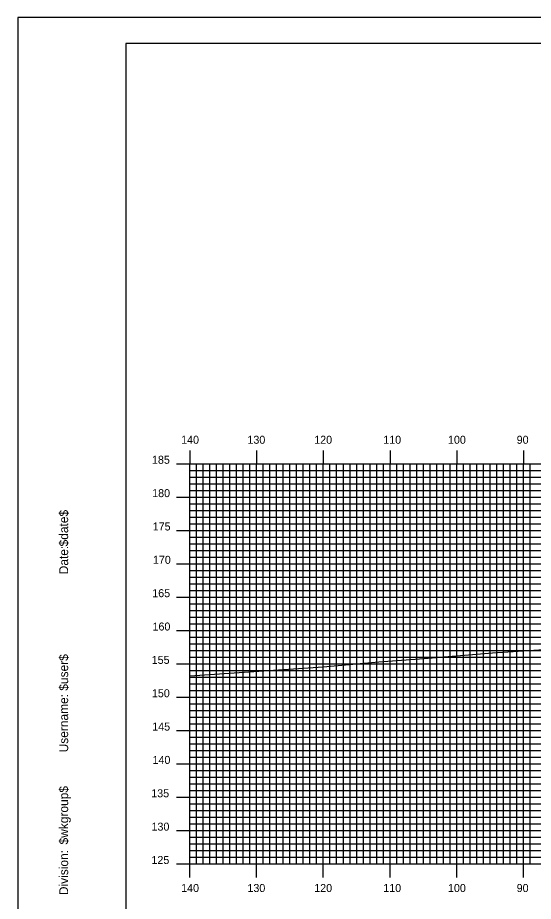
# Model space of a CAD drawing. Extents: x 1783828 to 1784171, y 442591 to 442811.
# Drawn here: x 1783827.7 to 1783905, y 442678.1 to 442810.5 of the extents above; entities that cross this region are included whole.
import ezdxf

# ---------------------------------------------------------------- set-up
doc = ezdxf.new("R2010")
doc.units = 0
for name, color, linetype in [('BORDER', 7, 'Continuous'), ('H_V ANNOTATION', 7, 'Continuous'), ('MAJOR', 7, 'Continuous'), ('MINOR', 7, 'Continuous'), ('PLOT BOUNDARY', 7, 'Continuous'), ('S_Roadway_Centerline', 7, 'Continuous')]:
    doc.layers.add(name, color=color, linetype=linetype)

msp = doc.modelspace()

# ---------------------------------------------------------------- linework, layer by layer
at = {"layer": 'BORDER'}
msp.add_lwpolyline([(1783843.89, 442596.67), (1784163.89, 442596.67), (1784163.89, 442806.67), (1783843.89, 442806.67)], close=True, dxfattribs=at)
at = {"layer": 'MAJOR'}
for p, q in [((1783853.49, 442745.67), (1783853.49, 442743.67)), ((1783863.49, 442745.67), (1783863.49, 442743.67)), ((1783873.49, 442745.67), (1783873.49, 442743.67)), ((1783883.49, 442745.67), (1783883.49, 442743.67)), ((1783893.49, 442745.67), (1783893.49, 442743.67)), ((1783903.49, 442745.67), (1783903.49, 442743.67)), ((1783851.48, 442743.67), (1783853.49, 442743.67)), ((1783853.49, 442743.67), (1784133.49, 442743.67)), ((1783853.49, 442683.67), (1783853.49, 442743.67)), ((1783853.49, 442683.67), (1783853.49, 442743.67)), ((1783853.49, 442743.67), (1784133.49, 442743.67)), ((1783863.49, 442683.67), (1783863.49, 442743.67)), ((1783873.49, 442683.67), (1783873.49, 442743.67)), ((1783883.49, 442683.67), (1783883.49, 442743.67)), ((1783893.49, 442683.67), (1783893.49, 442743.67)), ((1783903.49, 442683.67), (1783903.49, 442743.67)), ((1783851.48, 442738.67), (1783853.49, 442738.67)), ((1783853.49, 442738.67), (1784133.49, 442738.67)), ((1783851.48, 442733.67), (1783853.49, 442733.67)), ((1783853.49, 442733.67), (1784133.49, 442733.67)), ((1783851.48, 442728.67), (1783853.49, 442728.67)), ((1783853.49, 442728.67), (1784133.49, 442728.67)), ((1783851.48, 442723.67), (1783853.49, 442723.67)), ((1783853.49, 442723.67), (1784133.49, 442723.67)), ((1783851.48, 442718.67), (1783853.49, 442718.67)), ((1783853.49, 442718.67), (1784133.49, 442718.67)), ((1783851.48, 442713.67), (1783853.49, 442713.67)), ((1783853.49, 442713.67), (1784133.49, 442713.67)), ((1783851.48, 442708.67), (1783853.49, 442708.67)), ((1783853.49, 442708.67), (1784133.49, 442708.67)), ((1783851.48, 442703.67), (1783853.49, 442703.67)), ((1783853.49, 442703.67), (1784133.49, 442703.67)), ((1783851.48, 442698.67), (1783853.49, 442698.67)), ((1783853.49, 442698.67), (1784133.49, 442698.67)), ((1783851.48, 442693.67), (1783853.49, 442693.67)), ((1783853.49, 442693.67), (1784133.49, 442693.67)), ((1783851.48, 442688.67), (1783853.49, 442688.67)), ((1783853.49, 442688.67), (1784133.49, 442688.67)), ((1783851.48, 442683.67), (1783853.49, 442683.67)), ((1783853.49, 442683.67), (1784133.49, 442683.67)), ((1783853.49, 442683.67), (1784133.49, 442683.67)), ((1783853.49, 442681.66), (1783853.49, 442683.67)), ((1783863.49, 442681.66), (1783863.49, 442683.67)), ((1783873.49, 442681.66), (1783873.49, 442683.67)), ((1783883.49, 442681.66), (1783883.49, 442683.67)), ((1783893.49, 442681.66), (1783893.49, 442683.67)), ((1783903.49, 442681.66), (1783903.49, 442683.67))]:
    msp.add_line(p, q, dxfattribs=at)
at = {"layer": 'MINOR'}
for p, q in [((1783854.49, 442683.67), (1783854.49, 442743.67)), ((1783855.49, 442683.67), (1783855.49, 442743.67)), ((1783856.49, 442683.67), (1783856.49, 442743.67)), ((1783857.49, 442683.67), (1783857.49, 442743.67)), ((1783858.49, 442683.67), (1783858.49, 442743.67)), ((1783859.49, 442683.67), (1783859.49, 442743.67)), ((1783860.49, 442683.67), (1783860.49, 442743.67)), ((1783861.49, 442683.67), (1783861.49, 442743.67)), ((1783862.49, 442683.67), (1783862.49, 442743.67)), ((1783864.49, 442683.67), (1783864.49, 442743.67)), ((1783865.49, 442683.67), (1783865.49, 442743.67)), ((1783866.49, 442683.67), (1783866.49, 442743.67)), ((1783867.49, 442683.67), (1783867.49, 442743.67)), ((1783868.49, 442683.67), (1783868.49, 442743.67)), ((1783869.49, 442683.67), (1783869.49, 442743.67)), ((1783870.49, 442683.67), (1783870.49, 442743.67)), ((1783871.49, 442683.67), (1783871.49, 442743.67)), ((1783872.49, 442683.67), (1783872.49, 442743.67)), ((1783874.49, 442683.67), (1783874.49, 442743.67)), ((1783875.49, 442683.67), (1783875.49, 442743.67)), ((1783876.49, 442683.67), (1783876.49, 442743.67)), ((1783877.49, 442683.67), (1783877.49, 442743.67)), ((1783878.49, 442683.67), (1783878.49, 442743.67)), ((1783879.49, 442683.67), (1783879.49, 442743.67)), ((1783880.49, 442683.67), (1783880.49, 442743.67)), ((1783881.49, 442683.67), (1783881.49, 442743.67)), ((1783882.49, 442683.67), (1783882.49, 442743.67)), ((1783884.49, 442683.67), (1783884.49, 442743.67)), ((1783885.49, 442683.67), (1783885.49, 442743.67)), ((1783886.49, 442683.67), (1783886.49, 442743.67)), ((1783887.49, 442683.67), (1783887.49, 442743.67)), ((1783888.49, 442683.67), (1783888.49, 442743.67)), ((1783889.49, 442683.67), (1783889.49, 442743.67)), ((1783890.49, 442683.67), (1783890.49, 442743.67)), ((1783891.49, 442683.67), (1783891.49, 442743.67)), ((1783892.49, 442683.67), (1783892.49, 442743.67)), ((1783894.49, 442683.67), (1783894.49, 442743.67)), ((1783895.49, 442683.67), (1783895.49, 442743.67)), ((1783896.49, 442683.67), (1783896.49, 442743.67)), ((1783897.49, 442683.67), (1783897.49, 442743.67)), ((1783898.49, 442683.67), (1783898.49, 442743.67)), ((1783899.49, 442683.67), (1783899.49, 442743.67)), ((1783900.49, 442683.67), (1783900.49, 442743.67)), ((1783901.49, 442683.67), (1783901.49, 442743.67)), ((1783902.49, 442683.67), (1783902.49, 442743.67)), ((1783904.49, 442683.67), (1783904.49, 442743.67)), ((1783853.49, 442742.67), (1784133.49, 442742.67)), ((1783853.49, 442742.67), (1783855.49, 442742.67)), ((1783853.49, 442741.67), (1784133.49, 442741.67)), ((1783853.49, 442741.67), (1783855.49, 442741.67)), ((1783853.49, 442740.67), (1784133.49, 442740.67)), ((1783853.49, 442740.67), (1783855.49, 442740.67)), ((1783853.49, 442739.67), (1784133.49, 442739.67)), ((1783853.49, 442739.67), (1783855.49, 442739.67)), ((1783853.49, 442737.67), (1784133.49, 442737.67)), ((1783853.49, 442737.67), (1783855.49, 442737.67)), ((1783853.49, 442736.67), (1784133.49, 442736.67)), ((1783853.49, 442736.67), (1783855.49, 442736.67)), ((1783853.49, 442735.67), (1784133.49, 442735.67)), ((1783853.49, 442735.67), (1783855.49, 442735.67)), ((1783853.49, 442734.67), (1784133.49, 442734.67)), ((1783853.49, 442734.67), (1783855.49, 442734.67)), ((1783853.49, 442732.67), (1784133.49, 442732.67)), ((1783853.49, 442732.67), (1783855.49, 442732.67)), ((1783853.49, 442731.67), (1784133.49, 442731.67)), ((1783853.49, 442731.67), (1783855.49, 442731.67)), ((1783853.49, 442730.67), (1784133.49, 442730.67)), ((1783853.49, 442730.67), (1783855.49, 442730.67)), ((1783853.49, 442729.67), (1784133.49, 442729.67)), ((1783853.49, 442729.67), (1783855.49, 442729.67)), ((1783853.49, 442727.67), (1784133.49, 442727.67)), ((1783853.49, 442727.67), (1783855.49, 442727.67)), ((1783853.49, 442726.67), (1784133.49, 442726.67)), ((1783853.49, 442726.67), (1783855.49, 442726.67)), ((1783853.49, 442725.67), (1784133.49, 442725.67)), ((1783853.49, 442725.67), (1783855.49, 442725.67)), ((1783853.49, 442724.67), (1784133.49, 442724.67)), ((1783853.49, 442724.67), (1783855.49, 442724.67)), ((1783853.49, 442722.67), (1784133.49, 442722.67)), ((1783853.49, 442722.67), (1783855.49, 442722.67)), ((1783853.49, 442721.67), (1784133.49, 442721.67)), ((1783853.49, 442721.67), (1783855.49, 442721.67)), ((1783853.49, 442720.67), (1784133.49, 442720.67)), ((1783853.49, 442720.67), (1783855.49, 442720.67)), ((1783853.49, 442719.67), (1784133.49, 442719.67)), ((1783853.49, 442719.67), (1783855.49, 442719.67)), ((1783853.49, 442717.67), (1784133.49, 442717.67)), ((1783853.49, 442717.67), (1783855.49, 442717.67)), ((1783853.49, 442716.67), (1784133.49, 442716.67)), ((1783853.49, 442716.67), (1783855.49, 442716.67)), ((1783853.49, 442715.67), (1784133.49, 442715.67)), ((1783853.49, 442715.67), (1783855.49, 442715.67)), ((1783853.49, 442714.67), (1784133.49, 442714.67)), ((1783853.49, 442714.67), (1783855.49, 442714.67)), ((1783853.49, 442712.67), (1784133.49, 442712.67)), ((1783853.49, 442712.67), (1783855.49, 442712.67)), ((1783853.49, 442711.67), (1784133.49, 442711.67)), ((1783853.49, 442711.67), (1783855.49, 442711.67)), ((1783853.49, 442710.67), (1784133.49, 442710.67)), ((1783853.49, 442710.67), (1783855.49, 442710.67)), ((1783853.49, 442709.67), (1784133.49, 442709.67)), ((1783853.49, 442709.67), (1783855.49, 442709.67)), ((1783853.49, 442707.67), (1784133.49, 442707.67)), ((1783853.49, 442707.67), (1783855.49, 442707.67)), ((1783853.49, 442706.67), (1784133.49, 442706.67)), ((1783853.49, 442706.67), (1783855.49, 442706.67)), ((1783853.49, 442705.67), (1784133.49, 442705.67)), ((1783853.49, 442705.67), (1783855.49, 442705.67)), ((1783853.49, 442704.67), (1784133.49, 442704.67)), ((1783853.49, 442704.67), (1783855.49, 442704.67)), ((1783853.49, 442702.67), (1784133.49, 442702.67)), ((1783853.49, 442702.67), (1783855.49, 442702.67)), ((1783853.49, 442701.67), (1784133.49, 442701.67)), ((1783853.49, 442701.67), (1783855.49, 442701.67)), ((1783853.49, 442700.67), (1784133.49, 442700.67)), ((1783853.49, 442700.67), (1783855.49, 442700.67)), ((1783853.49, 442699.67), (1784133.49, 442699.67)), ((1783853.49, 442699.67), (1783855.49, 442699.67)), ((1783853.49, 442697.67), (1784133.49, 442697.67)), ((1783853.49, 442697.67), (1783855.49, 442697.67)), ((1783853.49, 442696.67), (1784133.49, 442696.67)), ((1783853.49, 442696.67), (1783855.49, 442696.67)), ((1783853.49, 442695.67), (1784133.49, 442695.67)), ((1783853.49, 442695.67), (1783855.49, 442695.67)), ((1783853.49, 442694.67), (1784133.49, 442694.67)), ((1783853.49, 442694.67), (1783855.49, 442694.67)), ((1783853.49, 442692.67), (1784133.49, 442692.67)), ((1783853.49, 442692.67), (1783855.49, 442692.67)), ((1783853.49, 442691.67), (1784133.49, 442691.67)), ((1783853.49, 442691.67), (1783855.49, 442691.67)), ((1783853.49, 442690.67), (1784133.49, 442690.67)), ((1783853.49, 442690.67), (1783855.49, 442690.67)), ((1783853.49, 442689.67), (1784133.49, 442689.67)), ((1783853.49, 442689.67), (1783855.49, 442689.67)), ((1783853.49, 442687.67), (1784133.49, 442687.67)), ((1783853.49, 442687.67), (1783855.49, 442687.67)), ((1783853.49, 442686.67), (1784133.49, 442686.67)), ((1783853.49, 442686.67), (1783855.49, 442686.67)), ((1783853.49, 442685.67), (1784133.49, 442685.67)), ((1783853.49, 442685.67), (1783855.49, 442685.67)), ((1783853.49, 442684.67), (1784133.49, 442684.67)), ((1783853.49, 442684.67), (1783855.49, 442684.67))]:
    msp.add_line(p, q, dxfattribs=at)
at = {"layer": 'PLOT BOUNDARY'}
msp.add_lwpolyline([(1783827.7, 442590.55), (1784167.7, 442590.55), (1784167.7, 442810.55), (1783827.7, 442810.55)], close=True, dxfattribs=at)
at = {"layer": 'S_Roadway_Centerline'}
msp.add_lwpolyline([(1783853.49, 442711.87), (1783866.8, 442712.79), (1783873.47, 442713.23), (1783881.83, 442713.97), (1783888.58, 442714.48), (1783898.84, 442715.31), (1783911.18, 442716.14), (1783921.63, 442717.01), (1783927.95, 442717.72), (1783934.33, 442718.23), (1783951.44, 442719.75), (1783956.09, 442720.05), (1783969.81, 442721.39), (1783974.44, 442721.86), (1783978.27, 442722.15), (1783993.21, 442723.6), (1783997.05, 442724.08), (1784000.91, 442724.38), (1784017.73, 442725.69), (1784024.01, 442726.23), (1784032.25, 442727.12)], dxfattribs=at)

# ---------------------------------------------------------------- texts
at = {"layer": 'BORDER'}
for s, p in [('$date$', (1783835.26, 442731.28)), ('$date$', (1783835.26, 442731.28)), ('Date:', (1783835.26, 442727.1)), ('Date:', (1783835.26, 442727.1)), ('$user$', (1783835.26, 442709.65)), ('$user$', (1783835.26, 442709.65)), ('Username:', (1783835.26, 442700.4)), ('Username:', (1783835.26, 442700.4)), ('$wkgroup$', (1783835.26, 442686.6)), ('$wkgroup$', (1783835.26, 442686.6)), ('Division:', (1783835.26, 442679)), ('Division:', (1783835.26, 442679))]:
    msp.add_text(s, height=1.339, rotation=90, dxfattribs=at).set_placement(p)
at = {"layer": 'H_V ANNOTATION'}
for s, p in [('140', (1783852.19, 442746.67)), ('130', (1783862.12, 442746.67)), ('120', (1783872.13, 442746.67)), ('110', (1783882.47, 442746.67)), ('100', (1783892.17, 442746.67)), ('90', (1783902.46, 442746.67)), ('185', (1783847.82, 442743.67)), ('180', (1783847.85, 442738.67)), ('175', (1783847.93, 442733.67)), ('170', (1783847.96, 442728.67)), ('165', (1783847.86, 442723.67)), ('160', (1783847.9, 442718.67)), ('155', (1783847.78, 442713.67)), ('150', (1783847.81, 442708.67)), ('145', (1783847.86, 442703.67)), ('140', (1783847.9, 442698.67)), ('135', (1783847.71, 442693.67)), ('130', (1783847.75, 442688.67)), ('125', (1783847.74, 442683.67)), ('140', (1783852.19, 442679.47)), ('130', (1783862.12, 442679.47)), ('120', (1783872.13, 442679.47)), ('110', (1783882.47, 442679.47)), ('100', (1783892.17, 442679.47)), ('90', (1783902.46, 442679.47))]:
    msp.add_text(s, height=1.2, dxfattribs=at).set_placement(p)
at = {"layer": 'MAJOR'}
msp.add_text('-', height=0.012, dxfattribs=at).set_placement((1783853.48, 442683.67))

doc.saveas('drawing.dxf')
